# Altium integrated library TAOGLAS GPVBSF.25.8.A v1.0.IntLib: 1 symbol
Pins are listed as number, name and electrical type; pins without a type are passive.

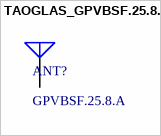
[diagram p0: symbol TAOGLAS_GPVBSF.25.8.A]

## TAOGLAS_GPVBSF.25.8.A
designator ANT?, comment GPVBSF.25.8.A
GPS L1 / L5 & BeiDou B1 Single Feed Stacked Patch Antenna; ComponentLibStatus: Created; MFG: Taoglas; Temp_High: +85C; Temp_Low: -40C
footprint TAOGLAS_GPVBSF.25.8.A (GPS L1 / L5 & BeiDou B1 Single Feed Stacked Patch Antenna)
pins: 1 RF FEED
